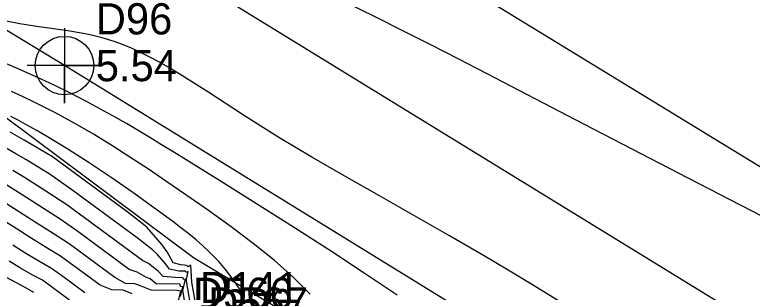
# Model space of a CAD drawing. Extents: x 2356077 to 2359823, y 225951 to 227822.
# Drawn here: x 2357198.6 to 2357257.6, y 226918.3 to 226940.5 of the extents above; entities that cross this region are included whole.
import ezdxf

# ---------------------------------------------------------------- set-up
doc = ezdxf.new("R2010")
doc.units = 0
for name, color, linetype in [('DTM Contours Major', 7, 'Continuous'), ('DTM Contours Minor', 7, 'Continuous'), ('Exist DTM Breakline Cogo Number', 7, 'Continuous'), ('Exist DTM Breakline Underwater Cogo Number', 7, 'Continuous'), ('Exist DTM Crownline', 7, 'Continuous'), ('Exist Roads EOP', 7, 'Continuous'), ('Exist Roads EOP Cogo Elevation', 7, 'Continuous'), ('Exist Roads EOP Cogo Number', 7, 'Continuous'), ('Exist Roads EOP Cogo Point CELL', 7, 'Continuous'), ('Exist Structure Minor Head and End Wall Cogo Number', 7, 'Continuous'), ('PH Exist DTM Breakline', 7, 'Continuous')]:
    doc.layers.add(name, color=color, linetype=linetype)

msp = doc.modelspace()

# ---------------------------------------------------------------- linework, layer by layer
at = {"layer": 'DTM Contours Major'}
for points in [[(2357216.862, 226918.146), (2357216.257, 226919.05), (2357215.993, 226919.42), (2357215.73, 226919.773), (2357215.466, 226920.111), (2357215.196, 226920.436), (2357214.92, 226920.751), (2357214.634, 226921.059), (2357214.155, 226921.539), (2357213.642, 226922.012), (2357213.095, 226922.484), (2357212.511, 226922.962), (2357211.888, 226923.451), (2357211.222, 226923.958), (2357209.696, 226925.086), (2357208.034, 226926.274), (2357206.297, 226927.479), (2357204.541, 226928.655), (2357202.825, 226929.762), (2357201.209, 226930.753), (2357200.294, 226931.285), (2357199.417, 226931.771), (2357198.833, 226932.08), (2357198.247, 226932.38)], [(2357211.532, 226916.933), (2357211.863, 226918.38), (2357211.573, 226918.427), (2357209.492, 226918.455), (2357208.706, 226918.764), (2357208.199, 226918.971), (2357207.456, 226918.981), (2357206.599, 226919.468), (2357202.942, 226922.16), (2357201.645, 226923), (2357200.293, 226923.856), (2357197.822, 226925.444)]]:
    msp.add_lwpolyline(points, dxfattribs=at)
at = {"layer": 'DTM Contours Minor'}
for points in [[(2357223.377, 226942.411), (2357227.527, 226940.339), (2357229.689, 226939.255), (2357231.884, 226938.142), (2357234.117, 226936.999), (2357236.391, 226935.827), (2357243.468, 226932.152), (2357252.48, 226927.475), (2357258.449, 226924.391)], [(2357245.68, 226915.422), (2357240.031, 226918.889), (2357238.106, 226920.057), (2357236.128, 226921.235), (2357233.396, 226922.823), (2357230.596, 226924.419), (2357227.786, 226926.011), (2357225.023, 226927.584), (2357222.364, 226929.125), (2357219.868, 226930.621), (2357218.295, 226931.599), (2357216.817, 226932.542), (2357214.121, 226934.292), (2357212.892, 226935.083), (2357211.733, 226935.808), (2357210.91, 226936.303), (2357210.117, 226936.757), (2357209.349, 226937.17), (2357208.6, 226937.545), (2357207.863, 226937.881), (2357207.134, 226938.179), (2357206.619, 226938.368), (2357206.1, 226938.539), (2357205.575, 226938.693), (2357205.038, 226938.832), (2357204.485, 226938.957), (2357203.913, 226939.068), (2357202.814, 226939.244), (2357200.351, 226939.589), (2357198.971, 226939.816), (2357197.48, 226940.117)], [(2357229.2, 226918.046), (2357226.653, 226919.767), (2357223.853, 226921.604), (2357220.911, 226923.495), (2357217.937, 226925.38), (2357215.041, 226927.196), (2357211.316, 226929.516), (2357210.337, 226930.121), (2357209.387, 226930.702), (2357208.455, 226931.263), (2357207.532, 226931.808), (2357206.607, 226932.34), (2357205.454, 226932.982), (2357204.268, 226933.616), (2357203.031, 226934.248), (2357201.727, 226934.886), (2357200.341, 226935.534), (2357198.854, 226936.199), (2357195.509, 226937.613)], [(2357222.226, 226918.133), (2357220.874, 226919.496), (2357219.341, 226920.855), (2357217.671, 226922.203), (2357215.909, 226923.531), (2357214.098, 226924.833), (2357212.283, 226926.101), (2357210.766, 226927.145), (2357209.273, 226928.155), (2357207.799, 226929.128), (2357206.339, 226930.062), (2357204.888, 226930.951), (2357203.443, 226931.795), (2357202.613, 226932.256), (2357201.778, 226932.704), (2357200.935, 226933.14), (2357200.078, 226933.565), (2357199.204, 226933.984), (2357198.307, 226934.396)], [(2357213.631, 226914.098), (2357212.762, 226919.087), (2357212.663, 226920.46), (2357212.471, 226920.314), (2357212.441, 226920.362), (2357212.389, 226920.404), (2357212.303, 226920.441), (2357212.156, 226920.473), (2357211.873, 226920.498), (2357211.253, 226920.66), (2357211.106, 226920.949), (2357210.945, 226921.237), (2357210.769, 226921.524), (2357210.577, 226921.811), (2357210.37, 226922.098), (2357209.146, 226923.505), (2357207.54, 226924.764), (2357201.597, 226929.135), (2357199.334, 226930.477), (2357198.195, 226931.124)], [(2357213.237, 226913.932), (2357212.325, 226919.168), (2357212.322, 226919.327), (2357212.468, 226919.961), (2357212.307, 226919.884), (2357212.251, 226919.974), (2357211.718, 226919.981), (2357210.975, 226920.151), (2357210.682, 226920.536), (2357210.358, 226920.92), (2357210.003, 226921.305), (2357209.617, 226921.695), (2357208.375, 226922.652), (2357203.148, 226926.5), (2357201.405, 226927.729), (2357199.451, 226928.922), (2357198.669, 226929.387), (2357197.884, 226929.846)], [(2357212.662, 226914.801), (2357212.034, 226918.422), (2357212.244, 226919.337), (2357212.089, 226919.309), (2357212.057, 226919.458), (2357211.415, 226919.466), (2357210.472, 226919.551), (2357210.055, 226919.983), (2357209.282, 226920.584), (2357208.805, 226920.838), (2357202.731, 226925.31), (2357201.072, 226926.403), (2357199.346, 226927.482), (2357198.431, 226928.045)], [(2357211.843, 226917.941), (2357212.023, 226918.727), (2357211.843, 226918.745), (2357211.823, 226918.942), (2357209.907, 226918.968), (2357209.411, 226919.364), (2357209.132, 226919.477), (2357208.385, 226919.907), (2357207.747, 226920.12), (2357203.619, 226923.159), (2357202.21, 226924.145), (2357199.156, 226926.093), (2357197.12, 226927.376)], [(2357207.967, 226918.168), (2357207.26, 226918.465), (2357206.362, 226918.477), (2357205.409, 226918.847), (2357202.247, 226921.172), (2357201.076, 226921.877), (2357199.883, 226922.619), (2357198.674, 226923.39), (2357197.491, 226924.16)], [(2357204.186, 226918.251), (2357202.425, 226919.547), (2357201.52, 226920.193), (2357200.501, 226920.78), (2357199.464, 226921.406), (2357198.412, 226922.066)], [(2357202.961, 226917.655), (2357200.795, 226919.25), (2357199.918, 226919.723), (2357199.028, 226920.229), (2357198.127, 226920.771)], [(2357200.1, 226918.264), (2357199.403, 226918.682), (2357198.662, 226919.068), (2357197.916, 226919.485)]]:
    msp.add_lwpolyline(points, dxfattribs=at)
at = {"layer": 'Exist DTM Crownline'}
msp.add_lwpolyline([(2357542.756, 226741.609), (2357459.889, 226792.427), (2357374.177, 226844.74), (2357291.426, 226895.083), (2357208.118, 226946.275), (2357125.882, 226996.539), (2357045.017, 227045.595), (2356966.337, 227093.498), (2356883.413, 227143.712), (2356799.704, 227194.618), (2356722.637, 227241.528), (2356636.765, 227293.74), (2356553.053, 227344.465), (2356470.397, 227394.758), (2356383.201, 227447.638), (2356299.889, 227498.478), (2356223.248, 227545.375)], dxfattribs=at)
at = {"layer": 'Exist Roads EOP'}
for points in [[(2357548.158, 226751.097), (2357465.654, 226801.744), (2357379.741, 226854.27), (2357296.317, 226905.048), (2357214.489, 226955.136), (2357131.706, 227005.719), (2357050.471, 227054.837), (2356971.347, 227103.361), (2356888.766, 227153.021), (2356805.008, 227204.071), (2356729.232, 227250.322), (2356641.873, 227303.321), (2356558.204, 227353.943), (2356475.441, 227404.348), (2356389.192, 227456.864), (2356305.906, 227507.596), (2356229.771, 227554.142)], [(2357548.158, 226751.097), (2357551.518, 226748.955), (2357539.932, 226730.044), (2357536.732, 226732.588), (2357457.094, 226780.918), (2357368.575, 226834.971), (2357285.95, 226885.112), (2357202.56, 226936.462), (2357119.743, 226986.718), (2357040.047, 227034.838), (2356959.55, 227083.993), (2356876.77, 227134.388), (2356794.33, 227184.148), (2356716.529, 227232.438), (2356632.17, 227283.448), (2356547.589, 227334.799), (2356465.16, 227384.805), (2356376.528, 227438.798), (2356293.908, 227488.913), (2356217.843, 227535.566)]]:
    msp.add_lwpolyline(points, dxfattribs=at)
at = {"layer": 'Exist Roads EOP Cogo Point CELL'}
msp.add_lwpolyline([(2357202.56, 226939.462), (2357202.56, 226933.462), (2357202.56, 226936.462), (2357205.56, 226936.462), (2357199.56, 226936.462)], dxfattribs=at)
msp.add_circle((2357202.56, 226936.462), 2.344, dxfattribs=at)
at = {"layer": 'PH Exist DTM Breakline'}
msp.add_lwpolyline([(2357134.751, 226970.426), (2357158.028, 226955.6), (2357176.952, 226945.122), (2357197.905, 226932.262), (2357212.892, 226921.066), (2357229.01, 226911.408), (2357243.825, 226903.007), (2357264.516, 226891.487), (2357285.525, 226878.969), (2357309.065, 226864.903), (2357332.833, 226850.108), (2357352.43, 226838.187), (2357373.686, 226825.25), (2357394.277, 226813), (2357414.012, 226801.184), (2357434.963, 226788.955), (2357455.092, 226776.87), (2357475.043, 226763.829)], dxfattribs=at)

# ---------------------------------------------------------------- texts
at = {"layer": 'Exist DTM Breakline Cogo Number'}
msp.add_text('D566', height=2.5, dxfattribs=at).set_placement((2357212.845, 226916.962))
at = {"layer": 'Exist DTM Breakline Underwater Cogo Number'}
msp.add_text('D567', height=2.5, dxfattribs=at).set_placement((2357214.073, 226916.181))
at = {"layer": 'Exist Roads EOP Cogo Elevation'}
msp.add_text('5.54', height=2.5, dxfattribs=at).set_placement((2357205.06, 226935.212))
at = {"layer": 'Exist Roads EOP Cogo Number'}
msp.add_text('D96', height=2.5, dxfattribs=at).set_placement((2357205.06, 226938.962))
at = {"layer": 'Exist Structure Minor Head and End Wall Cogo Number'}
msp.add_text('D141', height=2.5, dxfattribs=at).set_placement((2357213.397, 226917.415))

doc.saveas('drawing.dxf')
